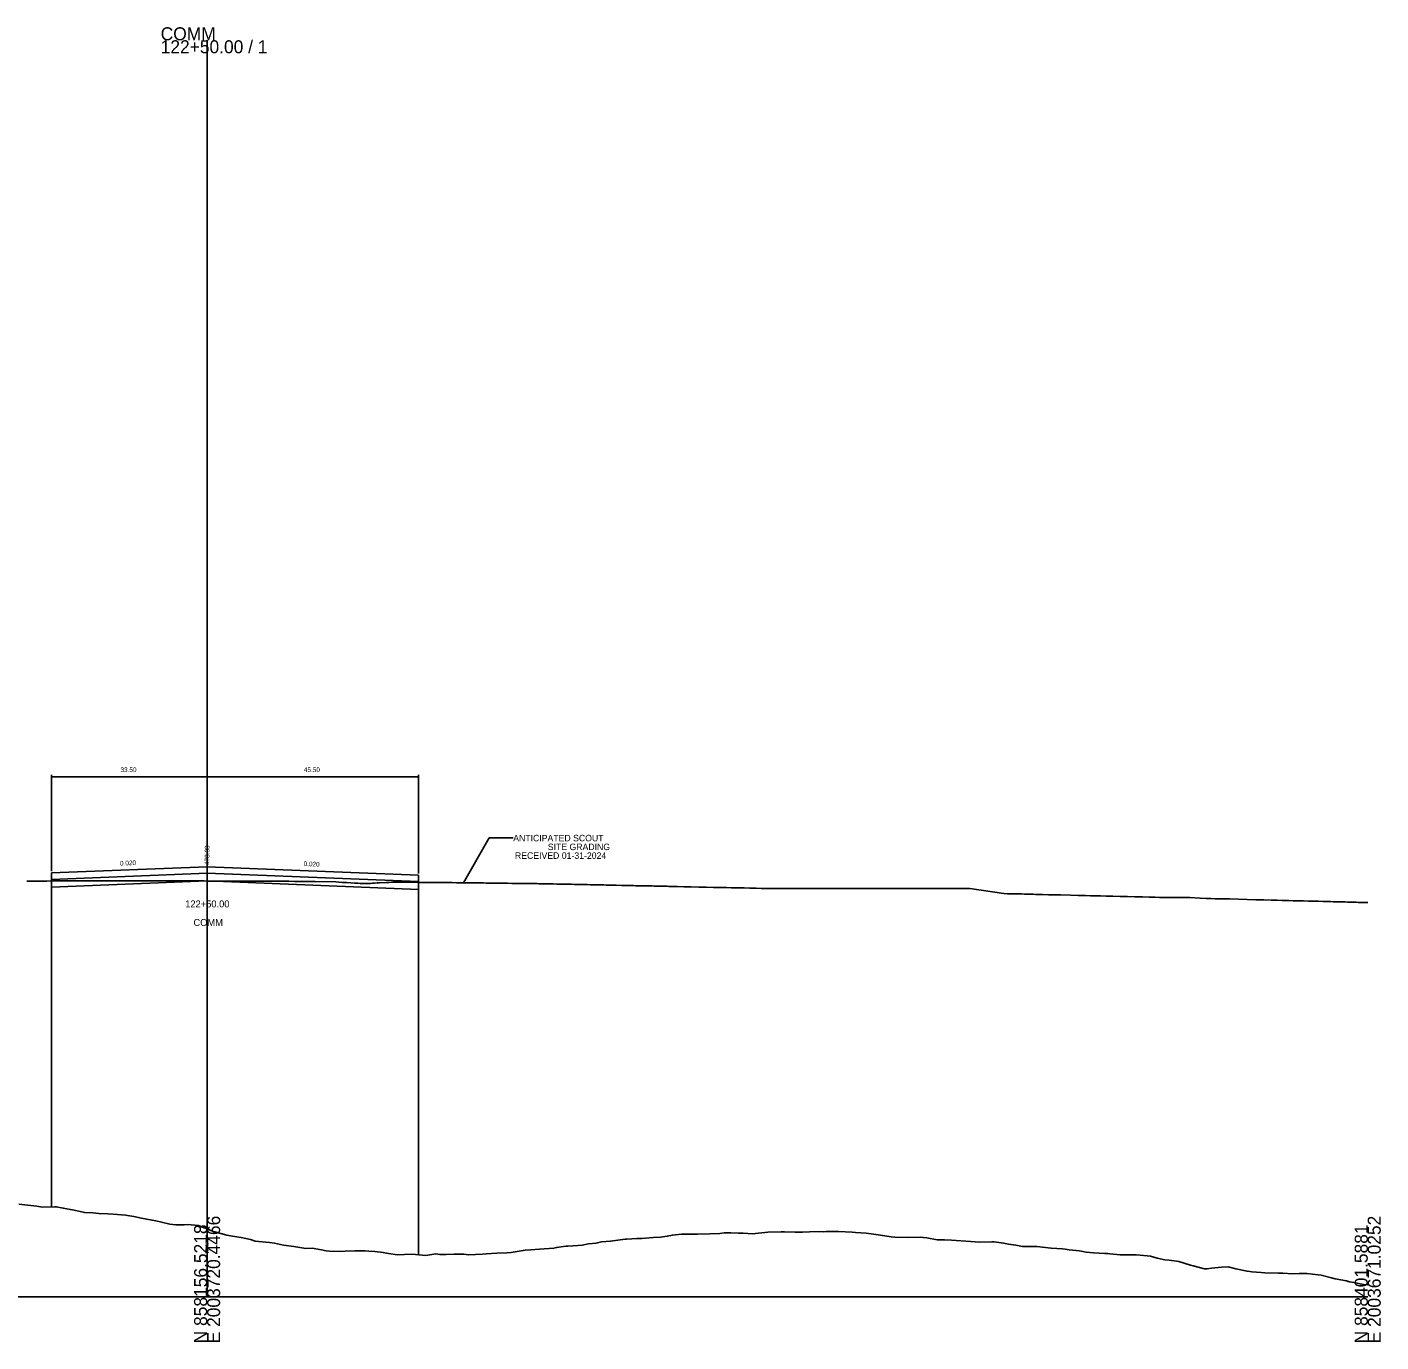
# Model space of a CAD drawing. Extents: x 2058594 to 2062449, y 841632 to 858028.
# Drawn here: x 2061157.7 to 2061449.4, y 856953.8 to 857237.1 of the extents above; entities that cross this region are included whole.
import ezdxf

# ---------------------------------------------------------------- set-up
doc = ezdxf.new("R2010")
doc.units = 0
for name, color, linetype in [('RD_DDB_Profile_Elev', 7, 'Continuous'), ('RD_GPK_XS_Cell', 7, 'Continuous'), ('RD_XS_Base', 7, 'Continuous'), ('RD_XS_EwShp1', 7, 'Continuous'), ('RD_XS_ExGround', 7, 'Continuous'), ('RD_XS_MatchLine', 7, 'Continuous'), ('RD_XS_Pave', 7, 'Continuous'), ('RD_XS_PaveShd', 7, 'Continuous'), ('RD_XS_TX_Elev_EX', 7, 'Continuous'), ('RD_XS_TX_Elev_PR', 7, 'Continuous'), ('RD_XS_TX_Misc', 7, 'Continuous'), ('RD_XS_TX_Slope', 7, 'Continuous'), ('RD_XS_TX_Station', 7, 'Continuous')]:
    doc.layers.add(name, color=color, linetype=linetype)

msp = doc.modelspace()

# ---------------------------------------------------------------- linework, layer by layer
at = {"layer": 'RD_DDB_Profile_Elev'}
for points in [[(2061262.4, 857062.38), (2061257.28, 857062.38), (2061251.71, 857052.73)], [(2061157.7, 857053.08), (2061159.11, 857053.09), (2061160.51, 857053.1), (2061162, 857053.11), (2061163.31, 857053.12), (2061164.56, 857053.12), (2061165.69, 857053.13), (2061166.33, 857053.13), (2061166.99, 857053.13), (2061167.3, 857053.14), (2061168.49, 857053.15), (2061169.85, 857053.15), (2061171.31, 857053.16), (2061172.82, 857053.16), (2061174.4, 857053.16), (2061175.95, 857053.17), (2061177.51, 857053.17), (2061179.47, 857053.18), (2061180.65, 857053.17), (2061181.62, 857053.17), (2061182.31, 857053.17), (2061183.52, 857053.17), (2061184.89, 857053.16), (2061186.38, 857053.15), (2061187.91, 857053.15), (2061189.57, 857053.14), (2061191.22, 857053.13), (2061192.66, 857053.13), (2061194, 857053.12), (2061194.89, 857053.12), (2061195.86, 857053.12), (2061196.55, 857053.11), (2061196.85, 857053.11), (2061198.09, 857053.11), (2061199.5, 857053.1), (2061201, 857053.1), (2061202.7, 857053.09), (2061204.31, 857053.09), (2061204.62, 857053.09), (2061205.93, 857053.08), (2061206.29, 857053.08), (2061207.5, 857053.08), (2061207.87, 857053.07), (2061208.92, 857053.07), (2061209.76, 857053.07), (2061210.14, 857053.07), (2061210.71, 857053.07), (2061211.34, 857053.06), (2061211.71, 857053.06), (2061212.54, 857053.06), (2061212.87, 857053.05), (2061214.11, 857053.05), (2061215.43, 857053.04), (2061216.71, 857053.04), (2061218.82, 857053.01), (2061219.81, 857053), (2061224.25, 857052.91), (2061224.85, 857052.87), (2061225.66, 857052.82), (2061226.56, 857052.77), (2061227.44, 857052.71), (2061228.26, 857052.66), (2061228.95, 857052.62), (2061229.48, 857052.58), (2061231.69, 857052.59), (2061232.1, 857052.62), (2061232.59, 857052.65), (2061233.11, 857052.69), (2061233.61, 857052.72), (2061235.12, 857052.81), (2061235.72, 857052.82), (2061236.23, 857052.83), (2061236.73, 857052.84), (2061237.16, 857052.84), (2061238.19, 857052.85), (2061238.64, 857052.85), (2061239.22, 857052.85), (2061239.83, 857052.84), (2061240.55, 857052.84), (2061241.09, 857052.83), (2061241.57, 857052.83), (2061242.29, 857052.82), (2061242.82, 857052.82), (2061243.71, 857052.81), (2061244.2, 857052.8), (2061245.21, 857052.79), (2061245.62, 857052.79), (2061245.93, 857052.79), (2061246.98, 857052.78), (2061247.29, 857052.77), (2061247.7, 857052.77), (2061248.75, 857052.76), (2061249.26, 857052.76), (2061250.25, 857052.75), (2061250.83, 857052.74), (2061251.71, 857052.73), (2061252.34, 857052.73), (2061253.06, 857052.72), (2061253.71, 857052.71), (2061254.22, 857052.71), (2061254.72, 857052.7), (2061255.36, 857052.69), (2061256.02, 857052.69), (2061256.63, 857052.68), (2061257.42, 857052.67), (2061257.96, 857052.66), (2061258.83, 857052.65), (2061259.28, 857052.65), (2061259.59, 857052.65), (2061260.5, 857052.63), (2061260.83, 857052.63), (2061261.25, 857052.63), (2061262.16, 857052.61), (2061262.64, 857052.61), (2061263.15, 857052.6), (2061264.03, 857052.59), (2061264.56, 857052.59), (2061265.38, 857052.58), (2061265.91, 857052.57), (2061266.41, 857052.56), (2061267.13, 857052.55), (2061267.57, 857052.55), (2061267.94, 857052.54), (2061268.31, 857052.54), (2061268.9, 857052.53), (2061269.45, 857052.52), (2061269.88, 857052.51), (2061270.59, 857052.5), (2061271.02, 857052.49), (2061271.85, 857052.47), (2061272.41, 857052.46), (2061273.34, 857052.44), (2061273.99, 857052.43), (2061274.98, 857052.41), (2061275.67, 857052.39), (2061276.69, 857052.37), (2061277.39, 857052.36), (2061278.38, 857052.34), (2061279.07, 857052.32), (2061279.96, 857052.3), (2061280.61, 857052.29), (2061281.37, 857052.27), (2061281.95, 857052.26), (2061282.5, 857052.25), (2061283.03, 857052.24), (2061283.53, 857052.23), (2061284.22, 857052.21), (2061284.62, 857052.2), (2061285.74, 857052.18), (2061286.97, 857052.15), (2061287.99, 857052.13), (2061288.35, 857052.12), (2061288.76, 857052.11), (2061289.82, 857052.09), (2061290.26, 857052.08), (2061291.32, 857052.06), (2061292.35, 857052.04), (2061292.78, 857052.03), (2061293.72, 857052.01), (2061294.13, 857052), (2061294.94, 857051.98), (2061295.58, 857051.97), (2061295.95, 857051.96), (2061296.61, 857051.94), (2061297.52, 857051.92), (2061297.83, 857051.92), (2061299.19, 857051.89), (2061300.77, 857051.85), (2061302.42, 857051.82), (2061303.99, 857051.78), (2061305.56, 857051.75), (2061307.06, 857051.72), (2061308.41, 857051.69), (2061309.44, 857051.67), (2061310.33, 857051.65), (2061311.09, 857051.63), (2061312.17, 857051.61), (2061313.41, 857051.58), (2061314.78, 857051.55), (2061315.88, 857051.53), (2061316.23, 857051.53), (2061317.73, 857051.53), (2061319.18, 857051.53), (2061320.54, 857051.53), (2061321.77, 857051.53), (2061322.86, 857051.53), (2061323.76, 857051.53), (2061324.52, 857051.53), (2061325.75, 857051.53), (2061327.2, 857051.53), (2061328.8, 857051.53), (2061330.45, 857051.53), (2061332.06, 857051.53), (2061333.75, 857051.53), (2061335.22, 857051.53), (2061336.26, 857051.53), (2061336.59, 857051.53), (2061337.45, 857051.53), (2061337.84, 857051.53), (2061338.47, 857051.53), (2061338.91, 857051.53), (2061339.54, 857051.53), (2061340.35, 857051.53), (2061340.83, 857051.53), (2061341.78, 857051.53), (2061342.27, 857051.53), (2061343.31, 857051.53), (2061343.8, 857051.53), (2061344.87, 857051.53), (2061345.33, 857051.53), (2061345.72, 857051.53), (2061346.79, 857051.53), (2061347.09, 857051.53), (2061348.1, 857051.53), (2061348.47, 857051.53), (2061348.99, 857051.53), (2061349.91, 857051.53), (2061350.55, 857051.53), (2061351.36, 857051.53), (2061352.08, 857051.53), (2061352.74, 857051.53), (2061353.22, 857051.53), (2061354, 857051.53), (2061354.47, 857051.53), (2061355.08, 857051.53), (2061355.86, 857051.53), (2061356.57, 857051.53), (2061357.29, 857051.53), (2061358.06, 857051.53), (2061358.67, 857051.53), (2061359.09, 857051.53), (2061360.06, 857051.53), (2061360.83, 857051.53), (2061368.15, 857050.4), (2061368.95, 857050.38), (2061369.67, 857050.37), (2061370.29, 857050.36), (2061370.78, 857050.34), (2061371.14, 857050.34), (2061371.48, 857050.33), (2061371.9, 857050.32), (2061372.58, 857050.3), (2061373.12, 857050.29), (2061373.63, 857050.28), (2061374.45, 857050.26), (2061374.96, 857050.24), (2061376.02, 857050.22), (2061376.51, 857050.2), (2061377.75, 857050.17), (2061378.21, 857050.16), (2061378.63, 857050.15), (2061379.99, 857050.12), (2061380.34, 857050.11), (2061382.48, 857050.05), (2061384.15, 857050.01), (2061385.43, 857049.98), (2061385.74, 857049.97), (2061386.81, 857049.94), (2061387.14, 857049.93), (2061387.89, 857049.91), (2061388.21, 857049.91), (2061388.92, 857049.89), (2061390.18, 857049.86), (2061391.62, 857049.83), (2061393.16, 857049.79), (2061394.76, 857049.75), (2061396.36, 857049.71), (2061397.97, 857049.68), (2061399.42, 857049.64), (2061400.7, 857049.61), (2061401.67, 857049.59), (2061402.36, 857049.57), (2061403.11, 857049.56), (2061404.06, 857049.54), (2061404.42, 857049.53), (2061405.09, 857049.53), (2061406.16, 857049.53), (2061407.25, 857049.53), (2061408.18, 857049.53), (2061410.4, 857049.39), (2061411.7, 857049.36), (2061412.73, 857049.34), (2061413.65, 857049.31), (2061415.03, 857049.28), (2061416.73, 857049.24), (2061418.6, 857049.19), (2061420.53, 857049.14), (2061422.4, 857049.09), (2061424.15, 857049.05), (2061425.71, 857049.01), (2061427.04, 857048.97), (2061428.09, 857048.94), (2061428.83, 857048.93), (2061429.54, 857048.91), (2061430.47, 857048.88), (2061431.53, 857048.86), (2061432.66, 857048.83), (2061433.79, 857048.8), (2061434.88, 857048.77), (2061435.89, 857048.74), (2061436.89, 857048.72), (2061437.24, 857048.71), (2061437.96, 857048.69), (2061438.5, 857048.68), (2061439.05, 857048.66), (2061439.38, 857048.65), (2061440.08, 857048.64), (2061440.42, 857048.63), (2061440.85, 857048.62), (2061441.68, 857048.6), (2061442.15, 857048.58), (2061442.64, 857048.57), (2061443.57, 857048.55), (2061444.04, 857048.53), (2061444.48, 857048.52), (2061445.47, 857048.5), (2061446.15, 857048.48), (2061446.51, 857048.47)]]:
    msp.add_lwpolyline(points, dxfattribs=at)
at = {"layer": 'RD_GPK_XS_Cell'}
for p, q in [((2061196.51, 856963.53), (2061196.51, 857234.21)), ((2061163.01, 857051.8), (2061196.51, 857053.14)), ((2060946.51, 856963.53), (2061196.51, 856963.53)), ((2061196.51, 856963.53), (2061446.51, 856963.53))]:
    msp.add_line(p, q, dxfattribs=at)
at = {"layer": 'RD_XS_Base'}
for p, q in [((2061163.01, 857051.8), (2061163.01, 857053.47)), ((2061163.01, 857051.8), (2061196.51, 857053.14)), ((2061196.51, 857053.14), (2061242.01, 857051.32)), ((2061242.01, 857051.32), (2061242.01, 857052.99))]:
    msp.add_line(p, q, dxfattribs=at)
at = {"layer": 'RD_XS_EwShp1'}
for p, q in [((2061196.51, 857053.14), (2061163.01, 857051.8)), ((2061163.01, 856982.93), (2061163.01, 857051.8)), ((2061196.51, 857053.14), (2061242.01, 857051.32)), ((2061242.01, 856972.6), (2061242.01, 857051.32))]:
    msp.add_line(p, q, dxfattribs=at)
at = {"layer": 'RD_XS_ExGround'}
msp.add_lwpolyline([(2061155.98, 856983.54), (2061157.9, 856983.3), (2061159.81, 856983.1), (2061160.96, 856982.88), (2061163.65, 856982.95), (2061164.02, 856982.95), (2061165.52, 856982.68), (2061167.08, 856982.35), (2061167.48, 856982.29), (2061170.14, 856981.68), (2061171.92, 856981.61), (2061173.21, 856981.49), (2061175.15, 856981.42), (2061176.27, 856981.33), (2061178.98, 856981.13), (2061179.33, 856981.07), (2061180.7, 856980.83), (2061182.39, 856980.5), (2061184.65, 856980.06), (2061185.45, 856979.95), (2061186.65, 856979.66), (2061188.51, 856979.17), (2061189.75, 856979.07), (2061191.57, 856979.05), (2061192.29, 856979.1), (2061194.63, 856978.89), (2061195.87, 856978.42), (2061196.51, 856978.16), (2061197.69, 856977.67), (2061198.15, 856977.57), (2061200.75, 856976.82), (2061201.99, 856976.65), (2061203.82, 856976.36), (2061205.82, 856975.89), (2061206.88, 856975.54), (2061209.94, 856975.26), (2061211.05, 856975.09), (2061213, 856974.7), (2061215.22, 856974.37), (2061216.06, 856974.22), (2061217.77, 856973.98), (2061219.12, 856974.02), (2061221.16, 856973.67), (2061222.18, 856973.47), (2061222.86, 856973.41), (2061225.24, 856973.31), (2061226.23, 856973.35), (2061228.3, 856973.44), (2061230.5, 856973.47), (2061231.36, 856973.35), (2061232.66, 856973.3), (2061234.42, 856973.1), (2061235.6, 856972.88), (2061237.49, 856972.57), (2061240.55, 856972.74), (2061241.41, 856972.65), (2061243.61, 856972.48), (2061245.79, 856972.8), (2061246.67, 856972.67), (2061248, 856972.63), (2061249.73, 856972.75), (2061251.83, 856972.73), (2061252.79, 856972.59), (2061255.85, 856972.76), (2061256.59, 856972.8), (2061258.91, 856972.93), (2061261.07, 856973.05), (2061261.97, 856973.11), (2061263.33, 856973.32), (2061265.03, 856973.59), (2061266.16, 856973.65), (2061268.1, 856973.79), (2061271.16, 856974.06), (2061271.77, 856974.15), (2061273.81, 856974.49), (2061274.22, 856974.49), (2061276.35, 856974.63), (2061277.28, 856974.71), (2061278.67, 856974.95), (2061280.34, 856975.14), (2061281.45, 856975.39), (2061283.4, 856975.57), (2061286.54, 856975.95), (2061286.95, 856975.97), (2061289.09, 856976.08), (2061289.52, 856976.11), (2061290.17, 856976.13), (2061292.58, 856976.34), (2061294.18, 856976.37), (2061295.64, 856976.59), (2061296.73, 856976.83), (2061298.7, 856977.06), (2061301.77, 856977.06), (2061302.12, 856977.08), (2061304.83, 856977.14), (2061306.92, 856977.19), (2061307.89, 856977.36), (2061309.34, 856977.33), (2061310.95, 856977.28), (2061312.01, 856977.24), (2061314.01, 856977.15), (2061317.3, 856977.51), (2061320.13, 856977.52), (2061320.85, 856977.53), (2061323.19, 856977.49), (2061324.75, 856977.49), (2061326.25, 856977.53), (2061328.51, 856977.6), (2061329.31, 856977.55), (2061329.85, 856977.63), (2061332.48, 856977.64), (2061335.44, 856977.48), (2061336.18, 856977.42), (2061338.5, 856977.29), (2061340.02, 856977.04), (2061341.56, 856976.8), (2061343.85, 856976.45), (2061344.62, 856976.42), (2061347.68, 856976.31), (2061350.22, 856976.42), (2061350.74, 856976.35), (2061351.52, 856976.24), (2061353.8, 856975.83), (2061355.35, 856975.8), (2061356.86, 856975.74), (2061357.87, 856975.71), (2061359.92, 856975.57), (2061362.98, 856975.29), (2061365.51, 856975.37), (2061366.05, 856975.42), (2061368.05, 856975.14), (2061369.11, 856974.92), (2061370.69, 856974.66), (2061372.17, 856974.38), (2061373.15, 856974.4), (2061375.23, 856974.37), (2061378.29, 856974), (2061380.79, 856973.87), (2061381.35, 856973.81), (2061382.19, 856973.68), (2061384.41, 856973.45), (2061385.89, 856973.14), (2061387.47, 856973.04), (2061389.86, 856972.88), (2061390.53, 856972.87), (2061390.98, 856972.81), (2061393.19, 856972.61), (2061393.7, 856972.58), (2061396.66, 856972.61), (2061397.53, 856972.5), (2061399.72, 856972.32), (2061401.17, 856971.87), (2061402.78, 856971.53), (2061403.72, 856971.46), (2061405.84, 856971.14), (2061408.37, 856970.4), (2061408.9, 856970.24), (2061411.36, 856969.58), (2061411.96, 856969.58), (2061412.87, 856969.75), (2061415.02, 856969.97), (2061416.45, 856969.99), (2061418.08, 856969.58), (2061420.53, 856969.07), (2061421.14, 856969), (2061421.55, 856968.95), (2061423.55, 856968.78), (2061424.37, 856968.72), (2061427.26, 856968.63), (2061428.2, 856968.65), (2061430.33, 856968.53), (2061431.74, 856968.58), (2061433.39, 856968.56), (2061435.87, 856968.27), (2061436.45, 856968.22), (2061438.73, 856967.63), (2061439.51, 856967.42), (2061441.92, 856966.97), (2061442.57, 856966.81), (2061443.54, 856966.62), (2061445.63, 856966.18), (2061446.51, 856966.12)], dxfattribs=at)
at = {"layer": 'RD_XS_MatchLine'}
for p, q in [((2061163.01, 857054.84), (2061163.01, 856982.93)), ((2061242.01, 857054.36), (2061242.01, 856972.6))]:
    msp.add_line(p, q, dxfattribs=at)
at = {"layer": 'RD_XS_Pave'}
for p, q in [((2061163.01, 857054.84), (2061196.51, 857056.18)), ((2061163.01, 857053.47), (2061196.51, 857054.81)), ((2061196.51, 857056.18), (2061242.01, 857054.36)), ((2061196.51, 857054.81), (2061242.01, 857052.99))]:
    msp.add_line(p, q, dxfattribs=at)
at = {"layer": 'RD_XS_PaveShd'}
for p, q in [((2061163.01, 857053.47), (2061163.01, 857054.84)), ((2061242.01, 857052.99), (2061242.01, 857054.36))]:
    msp.add_line(p, q, dxfattribs=at)
at = {"layer": 'RD_XS_TX_Misc'}
for p, q in [((2061163.01, 857075.98), (2061163.01, 857055.24)), ((2061163.01, 857075.58), (2061196.51, 857075.58)), ((2061196.51, 857075.98), (2061196.51, 857056.58)), ((2061196.51, 857075.58), (2061242.01, 857075.58)), ((2061242.01, 857075.98), (2061242.01, 857054.76))]:
    msp.add_line(p, q, dxfattribs=at)

# ---------------------------------------------------------------- texts
at = {"layer": 'RD_DDB_Profile_Elev'}
for s, p in [('ANTICIPATED SCOUT', (2061262.45, 857061.66)), ('SITE GRADING', (2061269.89, 857059.77)), ('RECEIVED 01-31-2024', (2061262.82, 857057.89))]:
    msp.add_text(s, height=1.4, dxfattribs=at).set_placement(p)
at = {"layer": 'RD_GPK_XS_Cell'}
for s, p in [('COMM', (2061186.51, 857234.21)), ('122+50.00 / 1', (2061186.51, 857231.41))]:
    msp.add_text(s, height=2.8, dxfattribs=at).set_placement(p)
for s, p in [('N 858156.5218', (2061196.51, 856953.53)), ('E 2003720.4466', (2061199.31, 856953.53)), ('N 858401.5881', (2061446.51, 856953.53)), ('E 2003671.0252', (2061449.31, 856953.53))]:
    msp.add_text(s, height=2.8, rotation=90, dxfattribs=at).set_placement(p)
at = {"layer": 'RD_XS_TX_Elev_EX'}
msp.add_text('439.31', height=0.8, rotation=270, dxfattribs=at).set_placement((2061196.11, 856976.16))
at = {"layer": 'RD_XS_TX_Elev_PR'}
msp.add_text(' 478.33', height=1, rotation=90, dxfattribs=at).set_placement((2061197.01, 857056.18))
at = {"layer": 'RD_XS_TX_Misc'}
for s, p in [('33.50', (2061177.85, 857076.58)), ('45.50', (2061217.35, 857076.58))]:
    msp.add_text(s, height=1, dxfattribs=at).set_placement(p)
at = {"layer": 'RD_XS_TX_Slope'}
for rotation, p in [(2.2906, (2061177.76, 857056.43)), (357.7094, (2061217.28, 857056.35))]:
    msp.add_text('0.020', height=1, rotation=rotation, dxfattribs=at).set_placement(p)
at = {"layer": 'RD_XS_TX_Station'}
for s, p in [('122+50.00', (2061191.79, 857047.43)), ('COMM', (2061193.57, 857043.43))]:
    msp.add_text(s, height=1.5, dxfattribs=at).set_placement(p)

doc.saveas('drawing.dxf')
